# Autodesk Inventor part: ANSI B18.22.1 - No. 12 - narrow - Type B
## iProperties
Comments: To add or edit properties for Autodesk Inventor files, use iProperties.
Created: 2005-01
Part Number: ANSI B18.22.1 - No. 12 - narrow - Type B
Vendor: Autodesk Inc.
Document SubType Name: Modeling
Designer: John Blackburn
Material: Default
Description: Washer B
Standard: ANSI B18.22.1
Size Designation: No. 12 - narrow - Type B
Alert: To add or edit properties for Autodesk Inventor files, use iProperties.
Control State: 0
Master: False
Checked Out: False
Shininess: 64.0
Length Units: 11272
Angle Units: 11279
Time Units: 11290
Mass Units: 11286
Length Display Precision: 3
Angle Display Precision: 2
Compacted: True
Classification: un/spsc 31161807
Density: 0.0
Volumn: 0.0
Area: 0.0
PropertySet Name: Model Information
Author: John Blackburn
Revision Number: 8
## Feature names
1. Body [Extrusion]
